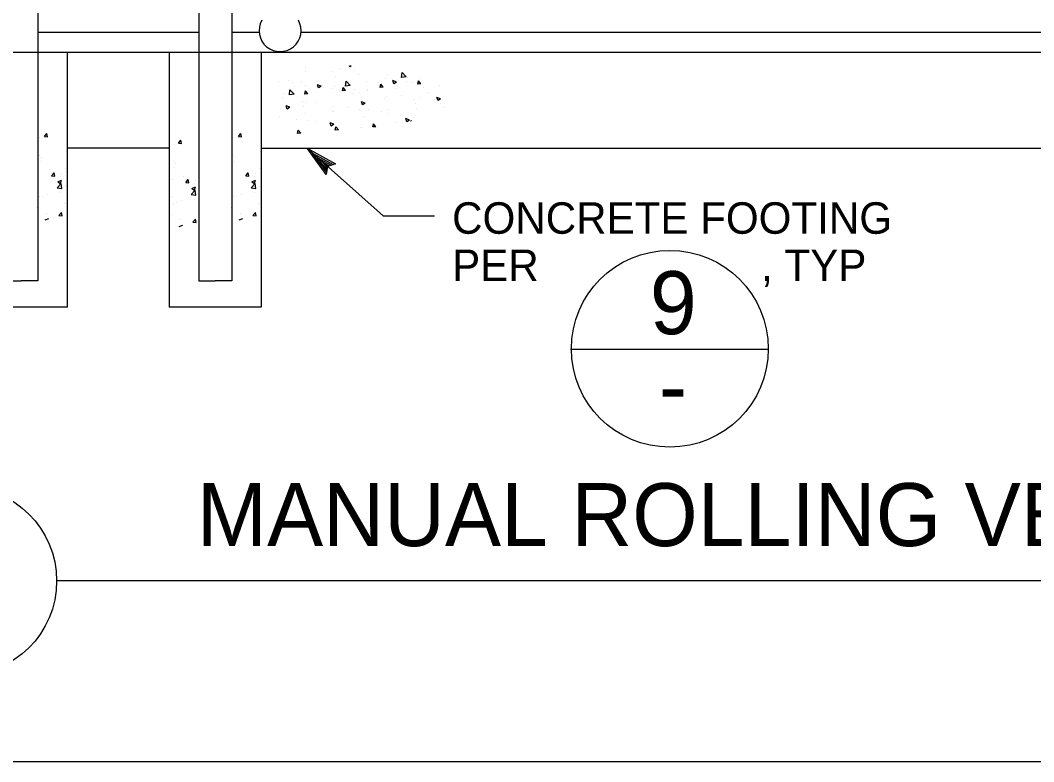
# Model space of a CAD drawing. Extents: x 6710407 to 6714861, y 1868090 to 1871317.
# Drawn here: x 6712158.9 to 6712351.9, y 1869155.1 to 1869296.4 of the extents above; entities that cross this region are included whole.
import ezdxf

# ---------------------------------------------------------------- set-up
doc = ezdxf.new("R2010")
doc.units = 0
for name, color, linetype in [('Erosion C (Lv35)', 7, 'Continuous'), ('G-MARK', 7, 'Continuous'), ('G-TEXT', 7, 'Continuous'), ('G-TTLB-VIEW', 7, 'Continuous'), ('Nongeo Data(60)', 7, 'Continuous')]:
    doc.layers.add(name, color=color, linetype=linetype)

# ---------------------------------------------------------------- blocks, each defined once
blk = doc.blocks.new('SC8415')
at = {"layer": 'Erosion C (Lv35)'}
for p, q in [((-1.69606, 1.76963), (-1.69579, 1.76945)), ((-1.69579, 1.76945), (-1.69573, 1.76963)), ((-1.69408, 1.76913), (-1.69408, 1.76913)), ((-1.68715, 1.76926), (-1.68715, 1.76926)), ((-1.70689, 1.76745), (-1.70689, 1.76745)), ((-1.70669, 1.76754), (-1.7059, 1.76836)), ((-1.70669, 1.76754), (-1.70579, 1.7674)), ((-1.70579, 1.7674), (-1.7059, 1.76836)), ((-1.70304, 1.76795), (-1.70304, 1.76795)), ((-1.6975, 1.7679), (-1.6975, 1.7679)), ((-1.69662, 1.7688), (-1.69662, 1.7688)), ((-1.69309, 1.7676), (-1.69309, 1.7676)), ((-1.69228, 1.76861), (-1.69228, 1.76861)), ((-1.68716, 1.76862), (-1.68716, 1.76862)), ((-1.71312, 1.76577), (-1.71312, 1.76577)), ((-1.71, 1.76543), (-1.71, 1.76543)), ((-1.70955, 1.76614), (-1.70906, 1.76672)), ((-1.70955, 1.76614), (-1.70894, 1.76608)), ((-1.70943, 1.76711), (-1.70943, 1.76711)), ((-1.70894, 1.76609), (-1.70906, 1.76672)), ((-1.70791, 1.76649), (-1.70791, 1.76649)), ((-1.70672, 1.76656), (-1.70672, 1.76656)), ((-1.70494, 1.76557), (-1.70494, 1.76557)), ((-1.70484, 1.76651), (-1.70412, 1.76679)), ((-1.70484, 1.76651), (-1.70433, 1.76617)), ((-1.70458, 1.7652), (-1.70458, 1.7652)), ((-1.70433, 1.76617), (-1.70412, 1.76679)), ((-1.70278, 1.76714), (-1.70278, 1.76714)), ((-1.70226, 1.7655), (-1.70177, 1.76608)), ((-1.70226, 1.7655), (-1.70165, 1.76545)), ((-1.70165, 1.76545), (-1.70177, 1.76609)), ((-1.7013, 1.76633), (-1.7013, 1.76633)), ((-1.69901, 1.76659), (-1.69901, 1.76659)), ((-1.69588, 1.7661), (-1.69588, 1.7661)), ((-1.69585, 1.76586), (-1.69506, 1.76668)), ((-1.69585, 1.76586), (-1.69494, 1.76572)), ((-1.69494, 1.76572), (-1.69506, 1.76668)), ((-1.69497, 1.76486), (-1.69449, 1.76545)), ((-1.69437, 1.76481), (-1.69448, 1.76545)), ((-1.6929, 1.76563), (-1.6929, 1.76563)), ((-1.69241, 1.76523), (-1.69241, 1.76523)), ((-1.69065, 1.76537), (-1.69065, 1.76537)), ((-1.69045, 1.76587), (-1.69045, 1.76587)), ((-1.69023, 1.7657), (-1.68952, 1.76597)), ((-1.69023, 1.7657), (-1.68973, 1.76536)), ((-1.68973, 1.76536), (-1.68952, 1.76597)), ((-1.68727, 1.76588), (-1.68727, 1.76588)), ((-1.68649, 1.76648), (-1.68649, 1.76648)), ((-1.68503, 1.76565), (-1.68503, 1.76565)), ((-1.68473, 1.76639), (-1.68473, 1.76639)), ((-1.68394, 1.76681), (-1.68394, 1.76681)), ((-1.682, 1.76664), (-1.682, 1.76664)), ((-1.71337, 1.76324), (-1.71266, 1.76351)), ((-1.71337, 1.76324), (-1.71287, 1.7629)), ((-1.71287, 1.7629), (-1.71266, 1.76351)), ((-1.71086, 1.76455), (-1.71086, 1.76455)), ((-1.70956, 1.76344), (-1.70956, 1.76344)), ((-1.70571, 1.76395), (-1.70571, 1.76395)), ((-1.7029, 1.76375), (-1.7029, 1.76375)), ((-1.7025, 1.76334), (-1.7025, 1.76334)), ((-1.6993, 1.76479), (-1.6993, 1.76479)), ((-1.69916, 1.76497), (-1.69916, 1.76497)), ((-1.69762, 1.76452), (-1.69762, 1.76452)), ((-1.69675, 1.76513), (-1.69675, 1.76513)), ((-1.69658, 1.76435), (-1.69658, 1.76435)), ((-1.69497, 1.76486), (-1.69437, 1.76481)), ((-1.69373, 1.76474), (-1.69373, 1.76474)), ((-1.68831, 1.76451), (-1.68831, 1.76451)), ((-1.68769, 1.76423), (-1.6872, 1.76481)), ((-1.68769, 1.76423), (-1.68708, 1.76417)), ((-1.68708, 1.76417), (-1.6872, 1.76481)), ((-1.685, 1.76418), (-1.68421, 1.765)), ((-1.685, 1.76418), (-1.6841, 1.76404)), ((-1.6841, 1.76404), (-1.68421, 1.765)), ((-1.68289, 1.76428), (-1.68289, 1.76428)), ((-1.68277, 1.76331), (-1.68277, 1.76331)), ((-1.71417, 1.76163), (-1.71417, 1.76163)), ((-1.71325, 1.76239), (-1.71325, 1.76239)), ((-1.7121, 1.7631), (-1.7121, 1.7631)), ((-1.70874, 1.7614), (-1.70874, 1.7614)), ((-1.70843, 1.76232), (-1.70843, 1.76232)), ((-1.70803, 1.7631), (-1.70803, 1.7631)), ((-1.69877, 1.76242), (-1.69806, 1.7627)), ((-1.69877, 1.76242), (-1.69827, 1.76208)), ((-1.69826, 1.76208), (-1.69806, 1.7627)), ((-1.69558, 1.76162), (-1.69558, 1.76162)), ((-1.69253, 1.76185), (-1.69253, 1.76185)), ((-1.68916, 1.76247), (-1.68916, 1.76247)), ((-1.6874, 1.7625), (-1.6874, 1.7625)), ((-1.68677, 1.76182), (-1.68677, 1.76182)), ((-1.68662, 1.7628), (-1.68662, 1.7628)), ((-1.68417, 1.76161), (-1.68346, 1.76188)), ((-1.68417, 1.76161), (-1.68366, 1.76127)), ((-1.68366, 1.76127), (-1.68346, 1.76188)), ((-1.70839, 1.75994), (-1.70839, 1.75994)), ((-1.70815, 1.75972), (-1.70815, 1.75972)), ((-1.70731, 1.75915), (-1.7066, 1.75942)), ((-1.7068, 1.75881), (-1.7066, 1.75942)), ((-1.70332, 1.76117), (-1.70332, 1.76117)), ((-1.70302, 1.76037), (-1.70302, 1.76037)), ((-1.70197, 1.76078), (-1.70197, 1.76078)), ((-1.69943, 1.76112), (-1.69943, 1.76112)), ((-1.69862, 1.75978), (-1.69862, 1.75978)), ((-1.6979, 1.76094), (-1.6979, 1.76094)), ((-1.69775, 1.76113), (-1.69775, 1.76113)), ((-1.6927, 1.7608), (-1.6927, 1.7608)), ((-1.69247, 1.76071), (-1.69247, 1.76071)), ((-1.68705, 1.76048), (-1.68705, 1.76048)), ((-1.68224, 1.75988), (-1.68224, 1.75988)), ((-1.70775, 1.75896), (-1.70765, 1.75908)), ((-1.70762, 1.7589), (-1.70765, 1.75908)), ((-1.70731, 1.75915), (-1.7068, 1.75881)), ((-1.70455, 1.75876), (-1.70455, 1.75876)), ((-1.70085, 1.75786), (-1.70036, 1.75844)), ((-1.70085, 1.75786), (-1.70025, 1.7578)), ((-1.70024, 1.75781), (-1.70036, 1.75844)), ((-1.69825, 1.75762), (-1.69825, 1.75762)), ((-1.69787, 1.75775), (-1.69787, 1.75775)), ((-1.69357, 1.75722), (-1.69308, 1.7578)), ((-1.69296, 1.75717), (-1.69307, 1.75781)), ((-1.69271, 1.75833), (-1.692, 1.75861)), ((-1.69271, 1.75833), (-1.6922, 1.75799)), ((-1.69265, 1.75847), (-1.69265, 1.75847)), ((-1.6922, 1.75799), (-1.69199, 1.75861)), ((-1.69183, 1.75846), (-1.69183, 1.75846)), ((-1.68929, 1.7588), (-1.68929, 1.7588)), ((-1.68752, 1.75912), (-1.68752, 1.75912)), ((-1.68544, 1.7593), (-1.68544, 1.7593)), ((-1.69357, 1.75722), (-1.69296, 1.75717)), ((-1.68628, 1.75658), (-1.68579, 1.75717)), ((-1.68628, 1.75658), (-1.68567, 1.75653)), ((-1.68567, 1.75653), (-1.68579, 1.75717))]:
    blk.add_line(p, q, dxfattribs=at)

msp = doc.modelspace()

# ---------------------------------------------------------------- linework, layer by layer
at = {"layer": 'G-MARK'}
for p, q in [((6712213.51, 1869272), (6712227.99, 1869259.11)), ((6712227.99, 1869259.11), (6712237.78, 1869259.11))]:
    msp.add_line(p, q, dxfattribs=at)
at = {"layer": 'G-TEXT'}
for p, q in [((6712217.1, 1869267.01), (6712213.51, 1869272)), ((6712213.51, 1869272), (6712213.51, 1869272)), ((6712213.51, 1869272), (6712218.88, 1869269)), ((6712217.18, 1869267.42), (6712214.54, 1869271.08)), ((6712214.55, 1869271.07), (6712218.46, 1869268.89)), ((6712217.24, 1869267.84), (6712215.57, 1869270.16)), ((6712215.57, 1869270.16), (6712218.1, 1869268.75)), ((6712217.34, 1869268.22), (6712216.6, 1869269.24)), ((6712216.6, 1869269.24), (6712217.69, 1869268.63)), ((6712217.4, 1869268.54), (6712217.1, 1869267.01)), ((6712218.88, 1869269), (6712217.4, 1869268.54)), ((6712218.88, 1869269), (6712218.88, 1869269)), ((6712217.1, 1869267.01), (6712217.1, 1869267.01))]:
    msp.add_line(p, q, dxfattribs=at)
at = {"layer": 'G-TTLB-VIEW'}
msp.add_lwpolyline([(6711433.78, 1870605.06), (6713227.53, 1870605.06), (6713227.53, 1869155.06), (6711433.78, 1869155.06)], close=True, dxfattribs=at)
at = {"layer": 'Nongeo Data(60)'}
for p, q in [((6712162.2, 1869340.58), (6712162.2, 1869246.7)), ((6712192.87, 1869340.58), (6712192.87, 1869246.7)), ((6712199.15, 1869340.58), (6712199.15, 1869246.7)), ((6712162.2, 1869294.11), (6712192.87, 1869294.11)), ((6712199.15, 1869294.11), (6712204.36, 1869294.11)), ((6712212.33, 1869294.11), (6712434.28, 1869294.11)), ((6712132.64, 1869290.29), (6712438.11, 1869290.29)), ((6712167.82, 1869290.29), (6712167.82, 1869253.71)), ((6712186.48, 1869290.29), (6712204.77, 1869290.29)), ((6712187.25, 1869290.29), (6712187.25, 1869253.71)), ((6712194.1, 1869290.29), (6712197.15, 1869290.29)), ((6712204.77, 1869290.29), (6712204.77, 1869253.71)), ((6712302.99, 1869290.29), (6712325.33, 1869290.29)), ((6712162.56, 1869274.02), (6712162.56, 1869274.02)), ((6712163.45, 1869274.22), (6712163.93, 1869274.8)), ((6712163.45, 1869274.22), (6712164.05, 1869274.17)), ((6712164.05, 1869274.17), (6712163.93, 1869274.8)), ((6712199.52, 1869274.02), (6712199.52, 1869274.02)), ((6712200.41, 1869274.22), (6712200.89, 1869274.8)), ((6712200.41, 1869274.22), (6712201.01, 1869274.17)), ((6712201.01, 1869274.17), (6712200.89, 1869274.8)), ((6712187.25, 1869272), (6712167.82, 1869272)), ((6712187.36, 1869272.46), (6712187.36, 1869272.46)), ((6712188.09, 1869272.76), (6712188.09, 1869272.76)), ((6712188.98, 1869272.96), (6712189.47, 1869273.53)), ((6712188.98, 1869272.96), (6712189.58, 1869272.9)), ((6712189.58, 1869272.9), (6712189.47, 1869273.53)), ((6712204.77, 1869272), (6712438.11, 1869272)), ((6712162.44, 1869270.7), (6712162.44, 1869270.7)), ((6712162.99, 1869270.28), (6712162.99, 1869270.28)), ((6712167.63, 1869271.44), (6712167.63, 1869271.44)), ((6712199.39, 1869270.7), (6712199.39, 1869270.7)), ((6712199.95, 1869270.28), (6712199.95, 1869270.28)), ((6712204.59, 1869271.44), (6712204.59, 1869271.44)), ((6712162.71, 1869269.54), (6712162.71, 1869269.54)), ((6712164.43, 1869267.88), (6712164.43, 1869267.88)), ((6712167.51, 1869268.12), (6712167.51, 1869268.12)), ((6712187.97, 1869269.43), (6712187.97, 1869269.43)), ((6712188.25, 1869268.27), (6712188.25, 1869268.27)), ((6712188.52, 1869269.01), (6712188.52, 1869269.01)), ((6712199.67, 1869269.54), (6712199.67, 1869269.54)), ((6712201.39, 1869267.88), (6712201.39, 1869267.88)), ((6712204.47, 1869268.12), (6712204.47, 1869268.12)), ((6712162.31, 1869267.37), (6712162.31, 1869267.37)), ((6712164.84, 1869266.7), (6712165.32, 1869267.28)), ((6712164.84, 1869266.7), (6712165.44, 1869266.65)), ((6712165.11, 1869267.34), (6712165.11, 1869267.34)), ((6712165.44, 1869266.65), (6712165.32, 1869267.28)), ((6712166.54, 1869266.53), (6712166.54, 1869266.53)), ((6712166.67, 1869267.17), (6712166.67, 1869267.17)), ((6712187.85, 1869266.1), (6712187.85, 1869266.1)), ((6712189.97, 1869266.61), (6712189.97, 1869266.61)), ((6712190.37, 1869265.43), (6712190.85, 1869266.01)), ((6712190.64, 1869266.08), (6712190.64, 1869266.08)), ((6712190.97, 1869265.38), (6712190.86, 1869266.01)), ((6712192.21, 1869265.9), (6712192.21, 1869265.9)), ((6712199.27, 1869267.37), (6712199.27, 1869267.37)), ((6712201.8, 1869266.7), (6712202.28, 1869267.28)), ((6712201.8, 1869266.7), (6712202.39, 1869266.65)), ((6712202.07, 1869267.34), (6712202.07, 1869267.34)), ((6712202.4, 1869266.65), (6712202.28, 1869267.28)), ((6712203.5, 1869266.53), (6712203.5, 1869266.53)), ((6712203.63, 1869267.17), (6712203.63, 1869267.17)), ((6712162.19, 1869264.04), (6712162.19, 1869264.04)), ((6712165.89, 1869264.44), (6712166.66, 1869265.25)), ((6712165.89, 1869264.44), (6712166.78, 1869264.3)), ((6712166.02, 1869265.61), (6712166.72, 1869265.88)), ((6712166.02, 1869265.61), (6712166.52, 1869265.28)), ((6712166.52, 1869265.28), (6712166.72, 1869265.88)), ((6712166.78, 1869264.3), (6712166.67, 1869265.25)), ((6712167.39, 1869264.79), (6712167.39, 1869264.79)), ((6712190.37, 1869265.43), (6712190.97, 1869265.38)), ((6712191.42, 1869263.17), (6712192.2, 1869263.99)), ((6712191.55, 1869264.34), (6712192.25, 1869264.61)), ((6712191.55, 1869264.34), (6712192.05, 1869264.01)), ((6712192.05, 1869264.01), (6712192.26, 1869264.61)), ((6712192.07, 1869265.27), (6712192.07, 1869265.27)), ((6712192.31, 1869263.04), (6712192.2, 1869263.99)), ((6712199.15, 1869264.04), (6712199.15, 1869264.04)), ((6712202.84, 1869264.44), (6712203.62, 1869265.25)), ((6712202.84, 1869264.44), (6712203.73, 1869264.3)), ((6712202.98, 1869265.61), (6712203.68, 1869265.88)), ((6712202.98, 1869265.61), (6712203.48, 1869265.28)), ((6712203.48, 1869265.28), (6712203.68, 1869265.88)), ((6712203.73, 1869264.3), (6712203.62, 1869265.25)), ((6712204.34, 1869264.79), (6712204.34, 1869264.79)), ((6712162.44, 1869262.79), (6712162.44, 1869262.79)), ((6712163.1, 1869262.84), (6712163.1, 1869262.84)), ((6712164.04, 1869263.22), (6712164.04, 1869263.22)), ((6712166.55, 1869263.55), (6712166.55, 1869263.55)), ((6712167.78, 1869262.57), (6712167.78, 1869262.57)), ((6712187.73, 1869262.77), (6712187.73, 1869262.77)), ((6712191.42, 1869263.17), (6712192.31, 1869263.04)), ((6712192.08, 1869262.28), (6712192.08, 1869262.28)), ((6712199.4, 1869262.79), (6712199.4, 1869262.79)), ((6712200.05, 1869262.84), (6712200.05, 1869262.84)), ((6712201, 1869263.22), (6712201, 1869263.22)), ((6712203.5, 1869263.55), (6712203.5, 1869263.55)), ((6712204.74, 1869262.57), (6712204.74, 1869262.57)), ((6712162.07, 1869260.71), (6712162.07, 1869260.71)), ((6712167.27, 1869261.46), (6712167.27, 1869261.46)), ((6712167.7, 1869260.11), (6712167.7, 1869260.11)), ((6712187.98, 1869261.53), (6712187.98, 1869261.53)), ((6712188.63, 1869261.58), (6712188.63, 1869261.58)), ((6712189.58, 1869261.96), (6712189.58, 1869261.96)), ((6712199.03, 1869260.71), (6712199.03, 1869260.71)), ((6712204.22, 1869261.46), (6712204.22, 1869261.46)), ((6712204.66, 1869260.11), (6712204.66, 1869260.11)), ((6712163.59, 1869258.36), (6712164.29, 1869258.63)), ((6712163.92, 1869259.61), (6712163.92, 1869259.61)), ((6712166.23, 1869259.18), (6712166.71, 1869259.75)), ((6712166.23, 1869259.18), (6712166.82, 1869259.13)), ((6712166.83, 1869259.13), (6712166.71, 1869259.75)), ((6712187.6, 1869259.44), (6712187.6, 1869259.44)), ((6712189.45, 1869258.34), (6712189.45, 1869258.34)), ((6712191.76, 1869257.91), (6712192.24, 1869258.49)), ((6712192.36, 1869257.86), (6712192.24, 1869258.49)), ((6712200.55, 1869258.36), (6712201.25, 1869258.63)), ((6712200.87, 1869259.61), (6712200.87, 1869259.61)), ((6712203.18, 1869259.18), (6712203.67, 1869259.75)), ((6712203.18, 1869259.18), (6712203.78, 1869259.13)), ((6712203.78, 1869259.13), (6712203.67, 1869259.75)), ((6712189.12, 1869257.09), (6712189.82, 1869257.36)), ((6712191.76, 1869257.91), (6712192.36, 1869257.86)), ((6712167.82, 1869253.71), (6712167.82, 1869241.71)), ((6712187.25, 1869253.71), (6712187.25, 1869241.71)), ((6712204.77, 1869253.71), (6712204.77, 1869241.71)), ((6712155.91, 1869246.7), (6712159.05, 1869246.7)), ((6712162.2, 1869246.7), (6712159.05, 1869246.7)), ((6712192.87, 1869246.7), (6712196.01, 1869246.7)), ((6712199.15, 1869246.7), (6712196.01, 1869246.7)), ((6712167.82, 1869241.71), (6712150.29, 1869241.71)), ((6712204.77, 1869241.71), (6712187.25, 1869241.71)), ((6712263.65, 1869233.72), (6712301.35, 1869233.72)), ((6712492.77, 1869189.52), (6712165.79, 1869189.52))]:
    msp.add_line(p, q, dxfattribs=at)
for centre, radius in [((6712282.6, 1869233.77), 18.75), ((6712147.79, 1869189.52), 18)]:
    msp.add_circle(centre, radius, dxfattribs=at)
msp.add_arc((6712208.35, 1869294.41), 4, 150.5121, 29.4879, dxfattribs=at)

# ---------------------------------------------------------------- block references
at = {"layer": 'Nongeo Data(60)', "xscale": 984.251968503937, "yscale": -984.251968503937, "rotation": 180}
msp.add_blockref('SC8415', (6710552.55, 1867545.92), dxfattribs=at)

# ---------------------------------------------------------------- texts
at = {"layer": 'Nongeo Data(60)'}
for s, height, p in [('CONCRETE FOOTING', 6, (6712241.12, 1869255.69)), ('PER                   , TYP', 6, (6712241.12, 1869246.69)), ('9', 12, (6712278.79, 1869236.55)), ('-', 12, (6712280.5, 1869220.72)), ('MANUAL ROLLING VEHICLE GATE', 12, (6712192.5, 1869196.16))]:
    msp.add_text(s, height=height, dxfattribs=at).set_placement(p)

doc.saveas('drawing.dxf')
